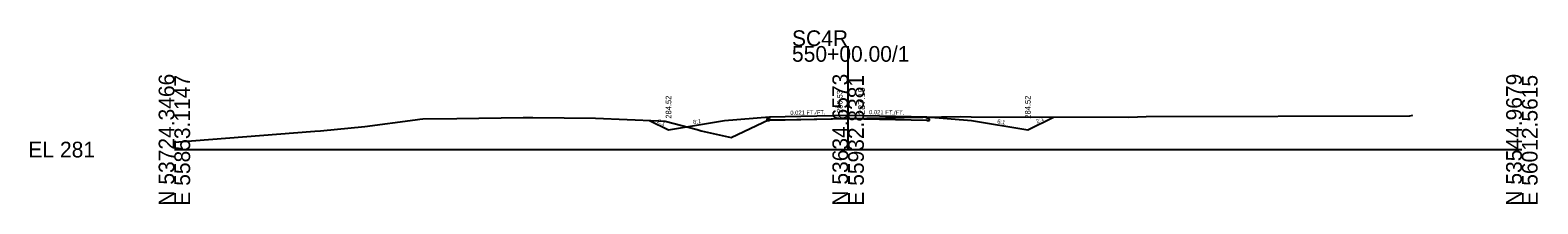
# Model space of a CAD drawing. Extents: x 9740 to 17409, y 8856 to 28416.
# Drawn here: x 12740.2 to 13008.7, y 10861.7 to 10892.7 of the extents above; entities that cross this region are included whole.
import ezdxf

# ---------------------------------------------------------------- set-up
doc = ezdxf.new("R2010")
doc.units = 0
for name, color, linetype in [('Level 10', 7, 'Continuous'), ('Level 11', 7, 'Continuous'), ('Level 12', 7, 'Continuous'), ('Level 32', 7, 'Continuous'), ('Level 33', 7, 'Continuous'), ('Level 59', 7, 'Continuous'), ('Level 6', 7, 'Continuous'), ('Level 60', 7, 'Continuous'), ('Level 63', 7, 'Continuous'), ('Level 7', 7, 'Continuous')]:
    doc.layers.add(name, color=color, linetype=linetype)

msp = doc.modelspace()

# ---------------------------------------------------------------- linework, layer by layer
at = {"layer": 'Level 11'}
for p, q in [((12871.85, 10876.93), (12871.35, 10876.92)), ((12871.35, 10876.92), (12871.35, 10876.58)), ((12871.35, 10876.58), (12871.85, 10876.59)), ((12871.85, 10877.23), (12871.85, 10876.93)), ((12899.85, 10876.93), (12899.85, 10877.23)), ((12900.35, 10876.92), (12899.85, 10876.93)), ((12899.85, 10876.59), (12900.35, 10876.58)), ((12900.35, 10876.58), (12900.35, 10876.92))]:
    msp.add_line(p, q, dxfattribs=at)
at = {"layer": 'Level 12'}
for p, q in [((12885.85, 10876.89), (12871.85, 10876.59)), ((12899.85, 10876.59), (12885.85, 10876.89))]:
    msp.add_line(p, q, dxfattribs=at)
at = {"layer": 'Level 59'}
for p, q in [((12871.85, 10877.23), (12885.85, 10877.53)), ((12885.85, 10877.53), (12899.85, 10877.23))]:
    msp.add_line(p, q, dxfattribs=at)
at = {"layer": 'Level 6'}
for p, q in [((12863.85, 10876.57), (12871.85, 10877.23)), ((12899.85, 10877.23), (12907.85, 10876.57))]:
    msp.add_line(p, q, dxfattribs=at)
at = {"layer": 'Level 60'}
for p, q in [((12799.78, 10875.48), (12808.73, 10876.69)), ((12808.73, 10876.69), (12809.57, 10876.82)), ((12809.57, 10876.82), (12810.08, 10876.84)), ((12810.08, 10876.84), (12816.18, 10876.94)), ((12816.18, 10876.94), (12828, 10877.13)), ((12828, 10877.13), (12828.89, 10877.13)), ((12828.89, 10877.13), (12829.72, 10877.13)), ((12829.72, 10877.13), (12840.85, 10877)), ((12840.85, 10877), (12852.11, 10876.51)), ((12852.11, 10876.51), (12852.93, 10876.47)), ((12852.93, 10876.47), (12853.26, 10876.42)), ((12853.26, 10876.42), (12858.96, 10874.97)), ((12865.03, 10873.51), (12871.8, 10876.75)), ((12871.8, 10876.75), (12873.71, 10876.68)), ((12873.71, 10876.68), (12885.85, 10876.91)), ((12885.85, 10876.91), (12905.78, 10877.28)), ((12905.78, 10877.28), (12907.75, 10877.22)), ((12907.75, 10877.22), (12935.82, 10877.16)), ((12935.82, 10877.16), (12938.93, 10877.26)), ((12938.93, 10877.26), (12985.87, 10877.42)), ((12985.87, 10877.42), (12986.45, 10877.54)), ((12765.85, 10872.7), (12790.85, 10874.66)), ((12790.85, 10874.66), (12791.87, 10874.75)), ((12791.87, 10874.75), (12799.78, 10875.48)), ((12858.96, 10874.97), (12859.68, 10874.73)), ((12859.68, 10874.73), (12865.03, 10873.51))]:
    msp.add_line(p, q, dxfattribs=at)
at = {"layer": 'Level 63'}
for p, q in [((12885.85, 10871.38), (12885.85, 10889.85)), ((12765.85, 10871.38), (12885.85, 10871.38)), ((12885.85, 10871.38), (13005.85, 10871.38))]:
    msp.add_line(p, q, dxfattribs=at)
at = {"layer": 'Level 7'}
for p, q in [((12850.5, 10876.58), (12853.85, 10874.9)), ((12853.85, 10874.9), (12863.85, 10876.57)), ((12907.85, 10876.57), (12917.85, 10874.9)), ((12917.85, 10874.9), (12922.43, 10877.19))]:
    msp.add_line(p, q, dxfattribs=at)

# ---------------------------------------------------------------- texts
at = {"layer": 'Level 10'}
msp.add_text('286.53', height=1, rotation=90, dxfattribs=at).set_placement((12884.85, 10877.91))
at = {"layer": 'Level 32'}
for s, rotation, p in [('0.021 FT./FT.', 1.1916, (12875.56, 10877.56)), ('0.021 FT./FT.', 358.8084, (12889.57, 10877.7)), ('2:1', 333.435, (12851.78, 10876.22)), ('6:1', 9.4623, (12858.29, 10875.89)), ('6:1', 350.5377, (12912.37, 10876.07)), ('2:1', 26.5651, (12919.52, 10876.02))]:
    msp.add_text(s, height=0.75, rotation=rotation, dxfattribs=at).set_placement(p)
at = {"layer": 'Level 33'}
for p in [(12854.35, 10876.9), (12918.35, 10876.9)]:
    msp.add_text('284.52', height=1, rotation=90, dxfattribs=at).set_placement(p)
at = {"layer": 'Level 59'}
msp.add_text(' 287.15', height=1.2, rotation=90, dxfattribs=at).set_placement((12888.84, 10877.12))
at = {"layer": 'Level 63'}
for s, p in [('SC4R', (12875.85, 10889.85)), ('550+00.00/1', (12875.85, 10887.05)), ('EL 281', (12739.85, 10869.98))]:
    msp.add_text(s, height=2.8, dxfattribs=at).set_placement(p)
for s, p in [('N 53724.3466', (12765.85, 10861.38)), ('E 55853.1147', (12768.65, 10861.38)), ('N 53634.6573', (12885.85, 10861.38)), ('E 55932.8381', (12888.65, 10861.38)), ('N 53544.9679', (13005.85, 10861.38)), ('E 56012.5615', (13008.65, 10861.38))]:
    msp.add_text(s, height=2.8, rotation=90, dxfattribs=at).set_placement(p)

doc.saveas('drawing.dxf')
